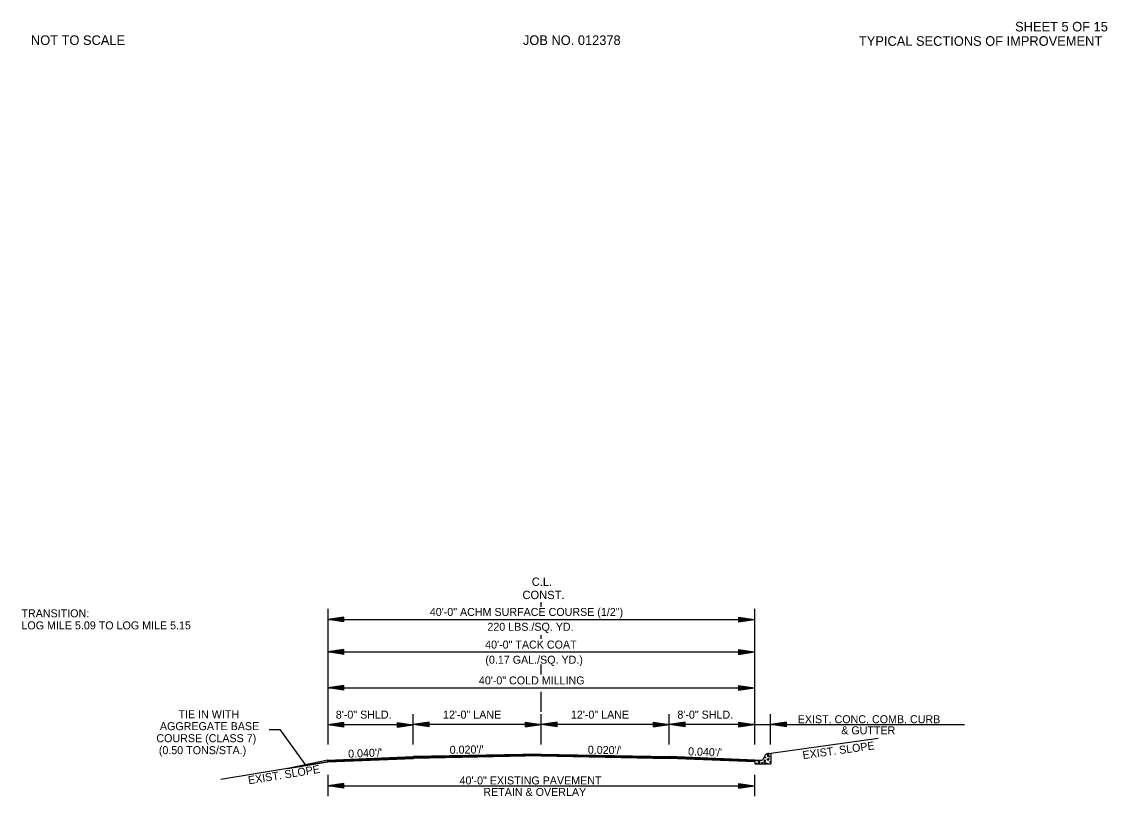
# Model space of a CAD drawing. Extents: x 542112 to 1930787, y -1968972 to 596640.
# Drawn here: x 546461 to 547479, y -1947632 to -1946906 of the extents above; entities that cross this region are included whole.
import ezdxf

# ---------------------------------------------------------------- set-up
doc = ezdxf.new("R2010")
doc.units = 0
doc.layers.add('R_Border Notes', color=7, linetype='Continuous')
doc.layers.add('R_Draft', color=7, linetype='Continuous')

msp = doc.modelspace()

# ---------------------------------------------------------------- linework, layer by layer
at = {"layer": 'R_Draft'}
for p, q in [((546947.9, -1947454.5), (546947.9, -1947450)), ((546747.9, -1947456.3), (546747.9, -1947583.7)), ((546762.9, -1947464), (546747.9, -1947466.2)), ((546747.9, -1947466.2), (547147.9, -1947466.2)), ((546762.9, -1947468.5), (546747.9, -1947466.2)), ((546762.9, -1947464.3), (546750.4, -1947466.2)), ((546762.9, -1947468.1), (546750.4, -1947466.2)), ((546762.9, -1947464.7), (546753, -1947466.2)), ((546762.9, -1947467.7), (546753, -1947466.2)), ((546762.9, -1947465.1), (546755.5, -1947466.2)), ((546762.9, -1947467.3), (546755.5, -1947466.2)), ((546762.9, -1947465.5), (546758.1, -1947466.2)), ((546762.9, -1947466.9), (546758.1, -1947466.2)), ((546762.9, -1947465.9), (546760.6, -1947466.2)), ((546762.9, -1947466.6), (546760.6, -1947466.2)), ((546762.9, -1947468.5), (546762.9, -1947464)), ((547132.9, -1947464), (547147.9, -1947466.2)), ((547132.9, -1947464), (547132.9, -1947468.5)), ((547132.9, -1947464.3), (547145.4, -1947466.2)), ((547132.9, -1947464.7), (547142.9, -1947466.2)), ((547132.9, -1947465.1), (547140.4, -1947466.2)), ((547132.9, -1947465.5), (547137.8, -1947466.2)), ((547132.9, -1947465.9), (547135.3, -1947466.2)), ((547132.9, -1947468.5), (547147.9, -1947466.2)), ((547132.9, -1947467), (547137.8, -1947466.2)), ((547132.9, -1947467.7), (547142.9, -1947466.2)), ((547132.9, -1947468.1), (547145.4, -1947466.2)), ((547132.9, -1947467.3), (547140.4, -1947466.2)), ((547132.9, -1947466.6), (547135.3, -1947466.2)), ((546947.9, -1947484.6), (546947.9, -1947480.9)), ((546762.9, -1947494.6), (546747.9, -1947496.8)), ((546747.9, -1947496.8), (547147.9, -1947496.8)), ((546762.9, -1947499.1), (546747.9, -1947496.8)), ((546762.9, -1947494.9), (546750.4, -1947496.8)), ((546762.9, -1947498.7), (546750.4, -1947496.8)), ((546762.9, -1947495.3), (546753, -1947496.8)), ((546762.9, -1947498.3), (546753, -1947496.8)), ((546762.9, -1947495.7), (546755.5, -1947496.8)), ((546762.9, -1947497.9), (546755.5, -1947496.8)), ((546762.9, -1947496.1), (546758.1, -1947496.8)), ((546762.9, -1947497.5), (546758.1, -1947496.8)), ((546762.9, -1947496.5), (546760.6, -1947496.8)), ((546762.9, -1947497.2), (546760.6, -1947496.8)), ((546762.9, -1947499.1), (546762.9, -1947494.6)), ((547132.9, -1947494.6), (547147.9, -1947496.8)), ((547132.9, -1947494.6), (547132.9, -1947499.1)), ((547132.9, -1947494.9), (547145.4, -1947496.8)), ((547132.9, -1947495.3), (547142.9, -1947496.8)), ((547132.9, -1947495.7), (547140.4, -1947496.8)), ((547132.9, -1947496.1), (547137.8, -1947496.8)), ((547132.9, -1947496.5), (547135.3, -1947496.8)), ((547132.9, -1947499.1), (547147.9, -1947496.8)), ((547132.9, -1947497.6), (547137.8, -1947496.8)), ((547132.9, -1947498.3), (547142.9, -1947496.8)), ((547132.9, -1947498.7), (547145.4, -1947496.8)), ((547132.9, -1947497.9), (547140.4, -1947496.8)), ((547132.9, -1947497.2), (547135.3, -1947496.8)), ((546947.9, -1947517.9), (546947.9, -1947508.6)), ((546762.9, -1947528.2), (546747.9, -1947530.4)), ((546747.9, -1947530.4), (547147.9, -1947530.4)), ((546762.9, -1947532.7), (546747.9, -1947530.4)), ((546762.9, -1947528.5), (546750.4, -1947530.4)), ((546762.9, -1947532.3), (546750.4, -1947530.4)), ((546762.9, -1947528.9), (546753, -1947530.4)), ((546762.9, -1947531.9), (546753, -1947530.4)), ((546762.9, -1947529.3), (546755.5, -1947530.4)), ((546762.9, -1947531.5), (546755.5, -1947530.4)), ((546762.9, -1947529.7), (546758.1, -1947530.4)), ((546762.9, -1947531.1), (546758.1, -1947530.4)), ((546762.9, -1947530.1), (546760.6, -1947530.4)), ((546762.9, -1947530.8), (546760.6, -1947530.4)), ((546762.9, -1947532.7), (546762.9, -1947528.2)), ((547132.9, -1947528.2), (547147.9, -1947530.4)), ((547132.9, -1947528.2), (547132.9, -1947532.7)), ((547132.9, -1947528.5), (547145.4, -1947530.4)), ((547132.9, -1947528.9), (547142.9, -1947530.4)), ((547132.9, -1947529.3), (547140.4, -1947530.4)), ((547132.9, -1947529.7), (547137.8, -1947530.4)), ((547132.9, -1947530.1), (547135.3, -1947530.4)), ((547132.9, -1947532.7), (547147.9, -1947530.4)), ((547132.9, -1947531.2), (547137.8, -1947530.4)), ((547132.9, -1947531.9), (547142.9, -1947530.4)), ((547132.9, -1947532.3), (547145.4, -1947530.4)), ((547132.9, -1947531.5), (547140.4, -1947530.4)), ((547132.9, -1947530.8), (547135.3, -1947530.4)), ((546947.9, -1947552.9), (546947.9, -1947534.1)), ((546762.7, -1947562.8), (546747.7, -1947565.1)), ((546762.7, -1947563.2), (546750.2, -1947565.1)), ((546762.7, -1947563.6), (546752.8, -1947565.1)), ((546762.7, -1947564), (546755.3, -1947565.1)), ((546762.7, -1947567.3), (546762.7, -1947562.8)), ((546812.9, -1947562.8), (546827.9, -1947565.1)), ((546812.9, -1947562.8), (546812.9, -1947567.3)), ((546812.9, -1947563.2), (546825.4, -1947565.1)), ((546812.9, -1947563.6), (546822.9, -1947565.1)), ((546812.9, -1947564), (546820.4, -1947565.1)), ((546827.9, -1947583.6), (546827.9, -1947555)), ((546827.9, -1947583.7), (546827.9, -1947555)), ((546842.9, -1947562.6), (546827.9, -1947564.9)), ((546842.9, -1947563), (546830.4, -1947564.9)), ((546842.9, -1947563.4), (546833, -1947564.9)), ((546842.9, -1947563.8), (546835.5, -1947564.9)), ((546842.9, -1947567.1), (546842.9, -1947562.6)), ((546932.9, -1947562.6), (546947.9, -1947564.9)), ((546932.9, -1947562.6), (546932.9, -1947567.1)), ((546932.9, -1947563), (546945.4, -1947564.9)), ((546932.9, -1947563.4), (546942.9, -1947564.9)), ((546932.9, -1947563.8), (546940.4, -1947564.9)), ((546947.9, -1947583.6), (546947.9, -1947555)), ((546962.9, -1947562.6), (546947.9, -1947564.9)), ((546962.9, -1947563), (546950.4, -1947564.9)), ((546962.9, -1947563.4), (546953, -1947564.9)), ((546962.9, -1947563.8), (546955.5, -1947564.9)), ((546962.9, -1947567.1), (546962.9, -1947562.6)), ((547052.9, -1947562.6), (547067.9, -1947564.9)), ((547052.9, -1947562.6), (547052.9, -1947567.1)), ((547052.9, -1947563), (547065.4, -1947564.9)), ((547052.9, -1947563.4), (547062.8, -1947564.9)), ((547052.9, -1947563.8), (547060.3, -1947564.9)), ((547067.9, -1947564.9), (547067.9, -1947555)), ((547067.9, -1947583.6), (547067.9, -1947555)), ((547082.9, -1947562.6), (547067.9, -1947564.9)), ((547082.9, -1947563), (547070.4, -1947564.9)), ((547082.9, -1947563.4), (547073, -1947564.9)), ((547082.9, -1947563.8), (547075.4, -1947564.9)), ((547082.9, -1947567.1), (547082.9, -1947562.6)), ((547132.9, -1947562.6), (547147.9, -1947564.9)), ((547132.9, -1947562.6), (547132.9, -1947567.1)), ((547132.9, -1947563), (547145.4, -1947564.9)), ((547132.9, -1947563.4), (547142.9, -1947564.9)), ((547132.9, -1947563.8), (547140.4, -1947564.9)), ((547162.9, -1947583.7), (547162.9, -1947555)), ((547177.9, -1947562.6), (547162.9, -1947564.9)), ((547177.9, -1947563), (547165.4, -1947564.9)), ((547177.9, -1947563.4), (547168, -1947564.9)), ((547177.9, -1947563.8), (547170.5, -1947564.9)), ((547177.9, -1947567.1), (547177.9, -1947562.6)), ((546762.7, -1947567.3), (546747.7, -1947565.1)), ((546827.9, -1947565.1), (546747.9, -1947565.1)), ((546762.7, -1947566.9), (546750.2, -1947565.1)), ((546762.7, -1947566.6), (546752.8, -1947565.1)), ((546762.7, -1947566.2), (546755.3, -1947565.1)), ((546762.7, -1947564.3), (546757.8, -1947565.1)), ((546762.7, -1947565.8), (546757.8, -1947565.1)), ((546762.7, -1947564.7), (546760.3, -1947565.1)), ((546762.7, -1947565.4), (546760.3, -1947565.1)), ((546812.9, -1947564.3), (546817.8, -1947565.1)), ((546812.9, -1947564.7), (546815.3, -1947565.1)), ((546812.9, -1947567.3), (546827.9, -1947565.1)), ((546812.9, -1947565.8), (546817.8, -1947565.1)), ((546812.9, -1947566.6), (546822.9, -1947565.1)), ((546812.9, -1947566.9), (546825.4, -1947565.1)), ((546812.9, -1947566.2), (546820.4, -1947565.1)), ((546812.9, -1947565.4), (546815.3, -1947565.1)), ((546947.9, -1947564.9), (546827.9, -1947564.9)), ((546842.9, -1947567.1), (546827.9, -1947564.9)), ((546842.9, -1947566.8), (546830.4, -1947564.9)), ((546842.9, -1947566.4), (546833, -1947564.9)), ((546842.9, -1947566), (546835.5, -1947564.9)), ((546842.9, -1947564.2), (546838.1, -1947564.9)), ((546842.9, -1947565.6), (546838.1, -1947564.9)), ((546842.9, -1947564.5), (546840.6, -1947564.9)), ((546842.9, -1947565.3), (546840.6, -1947564.9)), ((546932.9, -1947564.2), (546937.8, -1947564.9)), ((546932.9, -1947564.5), (546935.3, -1947564.9)), ((546932.9, -1947567.1), (546947.9, -1947564.9)), ((546932.9, -1947565.6), (546937.8, -1947564.9)), ((546932.9, -1947566.4), (546942.9, -1947564.9)), ((546932.9, -1947566.8), (546945.4, -1947564.9)), ((546932.9, -1947566), (546940.4, -1947564.9)), ((546932.9, -1947565.3), (546935.3, -1947564.9)), ((547067.9, -1947564.9), (546947.9, -1947564.9)), ((546962.9, -1947567.1), (546947.9, -1947564.9)), ((546962.9, -1947566.8), (546950.4, -1947564.9)), ((546962.9, -1947566.4), (546953, -1947564.9)), ((546962.9, -1947566), (546955.5, -1947564.9)), ((546962.9, -1947564.2), (546958.1, -1947564.9)), ((546962.9, -1947565.6), (546958.1, -1947564.9)), ((546962.9, -1947564.5), (546960.6, -1947564.9)), ((546962.9, -1947565.3), (546960.6, -1947564.9)), ((547052.9, -1947564.2), (547057.7, -1947564.9)), ((547052.9, -1947564.5), (547055.2, -1947564.9)), ((547052.9, -1947567.1), (547067.9, -1947564.9)), ((547052.9, -1947565.6), (547057.7, -1947564.9)), ((547052.9, -1947566.4), (547062.8, -1947564.9)), ((547052.9, -1947566.8), (547065.4, -1947564.9)), ((547052.9, -1947566), (547060.3, -1947564.9)), ((547052.9, -1947565.3), (547055.2, -1947564.9)), ((547067.9, -1947583.6), (547067.9, -1947564.9)), ((547147.9, -1947564.9), (547067.9, -1947564.9)), ((547082.9, -1947567.1), (547067.9, -1947564.9)), ((547082.9, -1947566.8), (547070.4, -1947564.9)), ((547082.9, -1947566.4), (547073, -1947564.9)), ((547082.9, -1947566), (547075.4, -1947564.9)), ((547082.9, -1947564.2), (547078, -1947564.9)), ((547082.9, -1947565.6), (547078, -1947564.9)), ((547082.9, -1947564.5), (547080.5, -1947564.9)), ((547082.9, -1947565.3), (547080.5, -1947564.9)), ((547132.9, -1947564.2), (547137.8, -1947564.9)), ((547132.9, -1947564.5), (547135.3, -1947564.9)), ((547132.9, -1947567.1), (547147.9, -1947564.9)), ((547132.9, -1947565.6), (547137.8, -1947564.9)), ((547132.9, -1947566.4), (547142.9, -1947564.9)), ((547132.9, -1947566.8), (547145.4, -1947564.9)), ((547132.9, -1947566), (547140.4, -1947564.9)), ((547132.9, -1947565.3), (547135.3, -1947564.9)), ((547147.9, -1947564.9), (547344.6, -1947564.9)), ((547177.9, -1947567.1), (547162.9, -1947564.9)), ((547177.9, -1947566.8), (547165.4, -1947564.9)), ((547177.9, -1947566.4), (547168, -1947564.9)), ((547177.9, -1947566), (547170.5, -1947564.9)), ((547177.9, -1947564.2), (547173.1, -1947564.9)), ((547177.9, -1947565.6), (547173.1, -1947564.9)), ((547177.9, -1947564.5), (547175.6, -1947564.9)), ((547177.9, -1947565.3), (547175.6, -1947564.9)), ((547263.7, -1947578), (547163.2, -1947591.9)), ((546947.9, -1947592.5), (546827.9, -1947594.9)), ((546947.9, -1947592.8), (546827.9, -1947595.2)), ((546948, -1947593.1), (546828, -1947595.5)), ((546948, -1947593.4), (546828, -1947595.8)), ((546948, -1947593.7), (546828, -1947596.1)), ((546948, -1947594), (546828, -1947596.4)), ((546948, -1947594.2), (546828, -1947596.6)), ((546947.9, -1947592.5), (547067.9, -1947594.9)), ((546947.9, -1947592.8), (547067.9, -1947595.2)), ((546947.9, -1947593.1), (547067.9, -1947595.5)), ((546947.9, -1947593.4), (547067.9, -1947595.8)), ((546947.9, -1947593.7), (547067.9, -1947596.1)), ((546947.9, -1947594), (547067.9, -1947596.4)), ((546947.9, -1947594.2), (547067.9, -1947596.6)), ((547158.2, -1947593.3), (547155.2, -1947598.1)), ((547161.1, -1947591.8), (547163.2, -1947591.9)), ((547163.2, -1947591.9), (547163.2, -1947601.6)), ((546747.7, -1947599.8), (546647.6, -1947616.5)), ((546747.7, -1947598.1), (546710.2, -1947606.1)), ((546710.2, -1947606.1), (546747.7, -1947599.8)), ((546747.7, -1947598.1), (546827.9, -1947594.9)), ((546747.7, -1947598.4), (546828, -1947595.2)), ((546747.7, -1947598.7), (546828, -1947595.5)), ((546747.7, -1947599), (546828, -1947595.8)), ((546747.7, -1947599.3), (546828, -1947596.1)), ((546747.7, -1947599.6), (546828, -1947596.4)), ((546747.7, -1947599.8), (546828, -1947596.6)), ((546747.7, -1947599.8), (546747.7, -1947598.1)), ((546747.7, -1947599.8), (546747.7, -1947598.1)), ((546747.7, -1947599.8), (546747.7, -1947598.1)), ((546747.7, -1947599.8), (546747.7, -1947599.8)), ((547148.2, -1947598.1), (547067.9, -1947594.9)), ((547148.2, -1947598.4), (547067.9, -1947595.2)), ((547148.2, -1947598.7), (547067.9, -1947595.5)), ((547148.2, -1947599), (547067.9, -1947595.8)), ((547148.2, -1947599.3), (547067.9, -1947596.1)), ((547148.2, -1947599.6), (547067.9, -1947596.4)), ((547148.2, -1947599.8), (547067.9, -1947596.6)), ((547148.2, -1947599.8), (547148.2, -1947598.1)), ((547148.2, -1947598.1), (547148.2, -1947599.8)), ((547148.2, -1947599.8), (547148.2, -1947598.1)), ((547148.2, -1947598.1), (547155.2, -1947598.1)), ((547148.2, -1947599.8), (547148.2, -1947598.1)), ((547148.2, -1947598.1), (547148.2, -1947599.8)), ((547148.2, -1947599.8), (547148.2, -1947598.1)), ((547148.2, -1947598.1), (547148.2, -1947601.6)), ((547148.2, -1947601.6), (547163.2, -1947601.6)), ((546747.9, -1947612.1), (546747.9, -1947632.1)), ((547147.9, -1947612.1), (547147.9, -1947632.1)), ((546762.9, -1947620.1), (546747.9, -1947622.4)), ((546747.9, -1947622.4), (547147.9, -1947622.4)), ((546762.9, -1947624.6), (546747.9, -1947622.4)), ((546762.9, -1947620.5), (546750.4, -1947622.4)), ((546762.9, -1947624.2), (546750.4, -1947622.4)), ((546762.9, -1947620.9), (546753, -1947622.4)), ((546762.9, -1947623.9), (546753, -1947622.4)), ((546762.9, -1947621.2), (546755.5, -1947622.4)), ((546762.9, -1947623.5), (546755.5, -1947622.4)), ((546762.9, -1947621.6), (546758.1, -1947622.4)), ((546762.9, -1947623.1), (546758.1, -1947622.4)), ((546762.9, -1947622), (546760.6, -1947622.4)), ((546762.9, -1947622.7), (546760.6, -1947622.4)), ((546762.9, -1947624.6), (546762.9, -1947620.1)), ((547132.9, -1947620.1), (547147.9, -1947622.4)), ((547132.9, -1947620.1), (547132.9, -1947624.6)), ((547132.9, -1947620.5), (547145.4, -1947622.4)), ((547132.9, -1947620.9), (547142.9, -1947622.4)), ((547132.9, -1947621.2), (547140.4, -1947622.4)), ((547132.9, -1947621.6), (547137.8, -1947622.4)), ((547132.9, -1947622), (547135.3, -1947622.4)), ((547132.9, -1947624.6), (547147.9, -1947622.4)), ((547132.9, -1947623.1), (547137.8, -1947622.4)), ((547132.9, -1947623.9), (547142.9, -1947622.4)), ((547132.9, -1947624.2), (547145.4, -1947622.4)), ((547132.9, -1947623.5), (547140.4, -1947622.4)), ((547132.9, -1947622.7), (547135.3, -1947622.4))]:
    msp.add_line(p, q, dxfattribs=at)
for points in [[(547147.9, -1947456.3), (547147.9, -1947583.6)], [(546692.8, -1947569.6), (546702.8, -1947569.6), (546726.2, -1947602.1)], [(547160.2, -1947595), (547161.4, -1947593.2), (547159.6, -1947592.8), (547160.2, -1947594.7)], [(547151.9, -1947601.6), (547153.1, -1947599.8), (547151.3, -1947599.4), (547151.9, -1947601.3)], [(547157.1, -1947601.3), (547158.2, -1947599.6), (547156.4, -1947599.2), (547157.1, -1947601.1)], [(547159.3, -1947597.2), (547161, -1947598.3), (547161.4, -1947596.6), (547159.5, -1947597.2)]]:
    msp.add_lwpolyline(points, dxfattribs=at)
for centre in [(547161.7, -1947594.9), (547149.6, -1947601.3), (547150.2, -1947598.5), (547152.4, -1947599), (547155, -1947600.8), (547157.7, -1947598.4), (547157.9, -1947595.8), (547159, -1947601.2), (547162.3, -1947599.9)]:
    msp.add_circle(centre, 0.339, dxfattribs=at)
msp.add_arc((547161, -1947595.1), 3.26, 88.8804, 147.7244, dxfattribs=at)

# ---------------------------------------------------------------- texts
at = {"layer": 'R_Border Notes'}
for s, p in [('SHEET 5 OF 15', (547392.1, -1946914.9)), ('NOT TO SCALE', (546469.5, -1946927.6)), ('TYPICAL SECTIONS OF IMPROVEMENT', (547245.7, -1946928.4))]:
    msp.add_text(s, height=9, dxfattribs=at).set_placement(p)
msp.add_text('JOB NO. 012378', height=9, rotation=360, dxfattribs=at).set_placement((546930.7, -1946927.6))
at = {"layer": 'R_Draft'}
for s, height, p in [('C.L.', 7.8, (546939, -1947434.8)), ('CONST.', 7.8, (546930.3, -1947447.2)), ('TRANSITION:', 7.5, (546460.6, -1947464.3)), ('40\'-0" ACHM SURFACE COURSE (1/2")', 7.5, (546843.4, -1947463)), ('LOG MILE 5.09 TO LOG MILE 5.15', 7.5, (546460.6, -1947475.6)), ('220 LBS./SQ. YD. ', 7.5, (546897.4, -1947476.9)), ('40\'-0" TACK COAT', 7.5, (546895.3, -1947493.6)), ('(0.17 GAL./SQ. YD.)', 7.5, (546895.5, -1947507.8)), ('40\'-0" COLD MILLING', 7.5, (546889.4, -1947527.2)), ('TIE IN WITH ', 7.5, (546607.8, -1947558.9)), ('8\'-0" SHLD.', 7.5, (546755.3, -1947559.3)), ('12\'-0" LANE', 7.5, (546855.8, -1947559.3)), ('12\'-0" LANE', 7.5, (546975.7, -1947559.3)), ('8\'-0" SHLD.', 7.5, (547075.5, -1947559.3)), ('AGGREGATE BASE', 7.5, (546590.4, -1947570.1)), ('EXIST. CONC. COMB. CURB', 7.5, (547188.3, -1947563.6)), ('COURSE (CLASS 7)', 7.5, (546587.1, -1947581.4)), ('& GUTTER ', 7.5, (547229.1, -1947574)), ('(0.50 TONS/STA.)', 7.5, (546589.4, -1947592.6)), ('40\'-0" EXISTING PAVEMENT', 7.5, (546871.3, -1947621)), ('RETAIN & OVERLAY', 7.5, (546893.6, -1947631.8))]:
    msp.add_text(s, height=height, dxfattribs=at).set_placement(p)
for s, rotation, p in [("0.020'/'", 0.8719, (546862.1, -1947592.3)), ('EXIST. SLOPE', 7.8318, (547193.4, -1947597.3)), ("0.040'/'", 2.448, (546767, -1947596)), ("0.020'/'", 359.164, (546991.5, -1947592.2)), ("0.040'/'", 357.8168, (547085.4, -1947593.6)), ('EXIST. SLOPE', 9.1534, (546673.7, -1947620.9))]:
    msp.add_text(s, height=7.5, rotation=rotation, dxfattribs=at).set_placement(p)

doc.saveas('drawing.dxf')
